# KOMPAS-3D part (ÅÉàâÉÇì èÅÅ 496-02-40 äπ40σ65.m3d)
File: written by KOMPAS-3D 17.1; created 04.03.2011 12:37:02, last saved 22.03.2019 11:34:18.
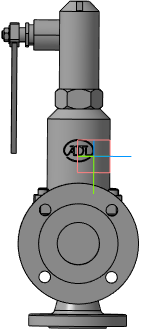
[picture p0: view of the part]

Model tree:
1. Плоскость XY
2. Плоскость ZX
3. Плоскость ZY
4. Ось X
5. Ось Y
6. Ось Z
7. Начало координат
8. Операция без истории:2

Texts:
  Viktor2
